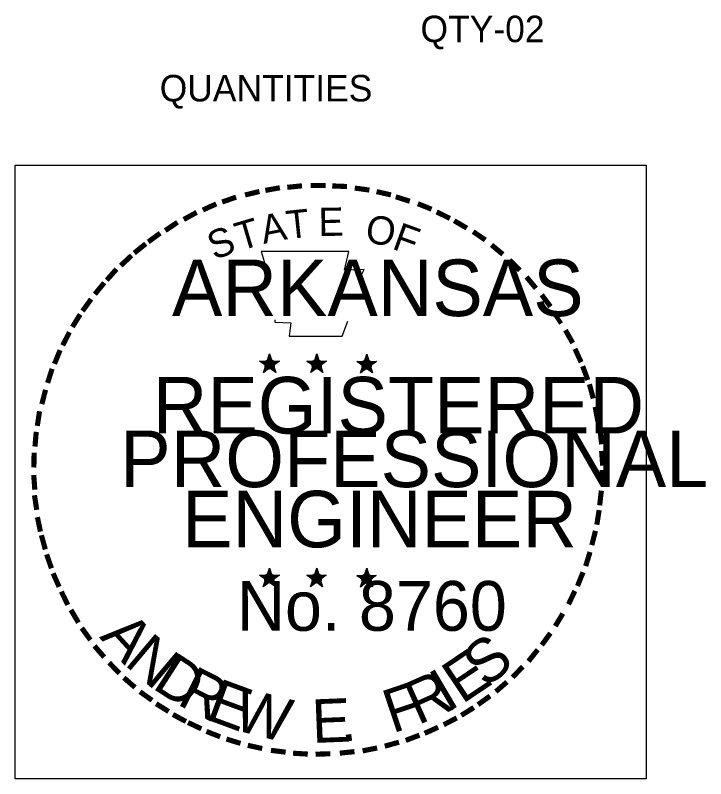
# Model space of a CAD drawing. Extents: x 1226657 to 1228145, y 151309 to 152305.
# Drawn here: x 1227992.6 to 1228145.3, y 152136.7 to 152305.5 of the extents above; entities that cross this region are included whole.
import ezdxf

# ---------------------------------------------------------------- set-up
doc = ezdxf.new("R2010")
doc.units = 0
for name, color, linetype in [('R_Border', 7, 'Continuous'), ('R_Border PE', 7, 'Continuous'), ('R_Border Prem', 7, 'Continuous')]:
    doc.layers.add(name, color=color, linetype=linetype)

msp = doc.modelspace()

# ---------------------------------------------------------------- linework, layer by layer
at = {"layer": 'R_Border PE'}
for p, q in [((1228048.84, 152230.69), (1228048.53, 152229.13)), ((1228048.84, 152230.69), (1228048.59, 152229.06)), ((1228048.84, 152230.69), (1228048.78, 152229.13)), ((1228048.84, 152228.38), (1228048.84, 152230.69)), ((1228048.84, 152230.69), (1228049.28, 152229.06)), ((1228048.84, 152230.69), (1228049.15, 152229.13)), ((1228048.84, 152230.69), (1228049.03, 152229.13)), ((1228059.28, 152230.69), (1228058.97, 152229.13)), ((1228059.28, 152230.69), (1228059.03, 152229.06)), ((1228059.28, 152230.69), (1228059.15, 152229.13)), ((1228059.28, 152228.38), (1228059.28, 152230.69)), ((1228059.28, 152230.69), (1228059.72, 152229.06)), ((1228059.28, 152230.69), (1228059.59, 152229.13)), ((1228059.28, 152230.69), (1228059.4, 152229.13)), ((1228070.34, 152230.56), (1228069.97, 152229.06)), ((1228070.34, 152230.56), (1228070.09, 152229)), ((1228070.34, 152230.56), (1228070.22, 152229)), ((1228070.34, 152228.31), (1228070.34, 152230.56)), ((1228070.34, 152230.56), (1228070.78, 152229)), ((1228070.34, 152230.56), (1228070.65, 152229)), ((1228070.34, 152230.56), (1228070.47, 152229.06)), ((1228046.65, 152229.06), (1228048.84, 152228.38)), ((1228046.65, 152229.06), (1228048.28, 152228.94)), ((1228046.65, 152229.06), (1228048.28, 152228.81)), ((1228046.65, 152229.06), (1228048.22, 152228.69)), ((1228046.65, 152229.06), (1228048.22, 152228.44)), ((1228046.65, 152229.06), (1228048.15, 152228.31)), ((1228046.65, 152229.06), (1228048.15, 152228.19)), ((1228047.53, 152226.5), (1228048.84, 152228.38)), ((1228047.53, 152226.5), (1228048.22, 152228.25)), ((1228047.53, 152226.5), (1228048.28, 152228.06)), ((1228047.53, 152226.5), (1228048.4, 152228)), ((1228047.53, 152226.5), (1228048.84, 152227.88)), ((1228047.53, 152226.5), (1228048.59, 152227.81)), ((1228047.53, 152226.5), (1228048.9, 152227.69)), ((1228051.03, 152229.06), (1228048.84, 152228.38)), ((1228050.22, 152226.5), (1228048.84, 152228.38)), ((1228050.22, 152226.5), (1228048.84, 152227.88)), ((1228050.22, 152226.5), (1228048.84, 152227.69)), ((1228051.03, 152229.06), (1228049.09, 152228.94)), ((1228050.22, 152226.5), (1228049.09, 152227.81)), ((1228051.03, 152229.06), (1228049.22, 152228.75)), ((1228051.03, 152229.06), (1228049.22, 152228.63)), ((1228050.22, 152226.5), (1228049.28, 152228.06)), ((1228050.22, 152226.5), (1228049.34, 152228.31)), ((1228050.22, 152226.5), (1228049.47, 152228.38)), ((1228051.03, 152229.06), (1228049.65, 152228.5)), ((1228051.03, 152229.06), (1228049.78, 152228.44)), ((1228051.03, 152229.06), (1228049.84, 152228.38)), ((1228057.09, 152229.06), (1228059.28, 152228.38)), ((1228057.09, 152229.06), (1228058.72, 152228.94)), ((1228057.09, 152229.06), (1228058.72, 152228.81)), ((1228057.09, 152229.06), (1228058.65, 152228.69)), ((1228057.09, 152229.06), (1228058.59, 152228.44)), ((1228057.09, 152229.06), (1228058.59, 152228.31)), ((1228057.09, 152229.06), (1228058.59, 152228.19)), ((1228057.97, 152226.5), (1228059.28, 152228.38)), ((1228057.97, 152226.5), (1228058.65, 152228.25)), ((1228057.97, 152226.5), (1228058.72, 152228.06)), ((1228057.97, 152226.5), (1228058.84, 152228)), ((1228057.97, 152226.5), (1228059.28, 152227.88)), ((1228057.97, 152226.5), (1228059.03, 152227.81)), ((1228057.97, 152226.5), (1228059.34, 152227.69)), ((1228061.47, 152229.06), (1228059.28, 152228.38)), ((1228060.65, 152226.5), (1228059.28, 152228.38)), ((1228060.65, 152226.5), (1228059.28, 152227.88)), ((1228060.65, 152226.5), (1228059.28, 152227.69)), ((1228061.47, 152229.06), (1228059.53, 152228.94)), ((1228060.65, 152226.5), (1228059.53, 152227.81)), ((1228061.47, 152229.06), (1228059.65, 152228.75)), ((1228061.47, 152229.06), (1228059.65, 152228.63)), ((1228060.65, 152226.5), (1228059.72, 152228.06)), ((1228060.65, 152226.5), (1228059.78, 152228.31)), ((1228060.65, 152226.5), (1228059.9, 152228.38)), ((1228061.47, 152229.06), (1228060.09, 152228.5)), ((1228061.47, 152229.06), (1228060.22, 152228.44)), ((1228061.47, 152229.06), (1228060.28, 152228.38)), ((1228068.15, 152229), (1228070.34, 152228.31)), ((1228068.15, 152229), (1228069.78, 152228.81)), ((1228068.15, 152229), (1228069.72, 152228.69)), ((1228068.15, 152229), (1228069.72, 152228.63)), ((1228068.15, 152229), (1228069.65, 152228.38)), ((1228068.15, 152229), (1228069.65, 152228.25)), ((1228068.15, 152229), (1228069.65, 152228.13)), ((1228068.97, 152226.44), (1228070.34, 152228.31)), ((1228068.97, 152226.44), (1228069.72, 152228.19)), ((1228068.97, 152226.44), (1228069.78, 152228)), ((1228068.97, 152226.44), (1228069.9, 152227.94)), ((1228068.97, 152226.44), (1228070.34, 152227.81)), ((1228068.97, 152226.44), (1228070.09, 152227.75)), ((1228068.97, 152226.44), (1228070.4, 152227.63)), ((1228072.53, 152229), (1228070.34, 152228.31)), ((1228071.65, 152226.44), (1228070.34, 152228.31)), ((1228071.65, 152226.44), (1228070.34, 152227.81)), ((1228071.65, 152226.44), (1228070.34, 152227.63)), ((1228072.53, 152229), (1228070.59, 152228.88)), ((1228071.65, 152226.44), (1228070.59, 152227.75)), ((1228072.53, 152229), (1228070.72, 152228.69)), ((1228072.53, 152229), (1228070.72, 152228.56)), ((1228071.65, 152226.44), (1228070.78, 152228)), ((1228071.65, 152226.44), (1228070.84, 152228.25)), ((1228071.65, 152226.44), (1228070.97, 152228.25)), ((1228072.53, 152229), (1228071.15, 152228.44)), ((1228072.53, 152229), (1228071.22, 152228.38)), ((1228072.53, 152229), (1228071.34, 152228.31)), ((1228048.84, 152183.31), (1228048.47, 152181.81)), ((1228048.84, 152183.31), (1228048.59, 152181.75)), ((1228048.84, 152183.31), (1228048.72, 152181.75)), ((1228048.84, 152181.06), (1228048.84, 152183.31)), ((1228048.84, 152183.31), (1228049.28, 152181.75)), ((1228048.84, 152183.31), (1228049.15, 152181.75)), ((1228048.84, 152183.31), (1228048.97, 152181.75)), ((1228059.28, 152183.31), (1228058.9, 152181.81)), ((1228059.28, 152183.31), (1228059.03, 152181.75)), ((1228059.28, 152183.31), (1228059.15, 152181.75)), ((1228059.28, 152181.06), (1228059.28, 152183.31)), ((1228059.28, 152183.31), (1228059.65, 152181.75)), ((1228059.28, 152183.31), (1228059.59, 152181.75)), ((1228059.28, 152183.31), (1228059.4, 152181.75)), ((1228070.34, 152183.25), (1228069.97, 152181.69)), ((1228070.34, 152183.25), (1228070.09, 152181.69)), ((1228070.34, 152183.25), (1228070.22, 152181.69)), ((1228070.34, 152181), (1228070.34, 152183.25)), ((1228070.34, 152183.25), (1228070.72, 152181.69)), ((1228070.34, 152183.25), (1228070.65, 152181.69)), ((1228070.34, 152183.25), (1228070.47, 152181.69)), ((1228046.65, 152181.75), (1228048.84, 152181.06)), ((1228046.65, 152181.75), (1228048.28, 152181.56)), ((1228046.65, 152181.75), (1228048.22, 152181.44)), ((1228046.65, 152181.75), (1228048.22, 152181.38)), ((1228046.65, 152181.75), (1228048.15, 152181.13)), ((1228046.65, 152181.75), (1228048.15, 152181)), ((1228046.65, 152181.75), (1228048.15, 152180.88)), ((1228047.47, 152179.19), (1228048.84, 152181.06)), ((1228047.47, 152179.19), (1228048.22, 152180.94)), ((1228047.47, 152179.19), (1228048.28, 152180.69)), ((1228047.47, 152179.19), (1228048.4, 152180.63)), ((1228047.47, 152179.19), (1228048.84, 152180.56)), ((1228047.47, 152179.19), (1228048.59, 152180.5)), ((1228047.47, 152179.19), (1228048.84, 152180.38)), ((1228050.15, 152179.19), (1228048.78, 152180.38)), ((1228051.03, 152181.75), (1228048.84, 152181.06)), ((1228050.15, 152179.19), (1228048.84, 152181.06)), ((1228050.15, 152179.19), (1228048.84, 152180.5)), ((1228050.15, 152179.19), (1228049.03, 152180.5)), ((1228051.03, 152181.75), (1228049.09, 152181.63)), ((1228051.03, 152181.75), (1228049.22, 152181.44)), ((1228051.03, 152181.75), (1228049.22, 152181.31)), ((1228050.15, 152179.19), (1228049.28, 152181)), ((1228050.15, 152179.19), (1228049.28, 152180.75)), ((1228050.15, 152179.19), (1228049.47, 152181)), ((1228051.03, 152181.75), (1228049.59, 152181.19)), ((1228051.03, 152181.75), (1228049.72, 152181.13)), ((1228051.03, 152181.75), (1228049.84, 152181)), ((1228057.09, 152181.75), (1228059.28, 152181.06)), ((1228057.09, 152181.75), (1228058.65, 152181.56)), ((1228057.09, 152181.75), (1228058.65, 152181.44)), ((1228057.09, 152181.75), (1228058.65, 152181.38)), ((1228057.09, 152181.75), (1228058.59, 152181.13)), ((1228057.09, 152181.75), (1228058.59, 152181)), ((1228057.09, 152181.75), (1228058.59, 152180.88)), ((1228057.9, 152179.19), (1228059.28, 152181.06)), ((1228057.9, 152179.19), (1228058.65, 152180.94)), ((1228057.9, 152179.19), (1228058.72, 152180.69)), ((1228057.9, 152179.19), (1228058.84, 152180.63)), ((1228057.9, 152179.19), (1228059.28, 152180.56)), ((1228057.9, 152179.19), (1228059.03, 152180.5)), ((1228057.9, 152179.19), (1228059.28, 152180.38)), ((1228060.59, 152179.19), (1228059.22, 152180.38)), ((1228061.4, 152181.75), (1228059.28, 152181.06)), ((1228060.59, 152179.19), (1228059.28, 152181.06)), ((1228060.59, 152179.19), (1228059.28, 152180.5)), ((1228060.59, 152179.19), (1228059.47, 152180.5)), ((1228061.4, 152181.75), (1228059.53, 152181.63)), ((1228061.4, 152181.75), (1228059.65, 152181.44)), ((1228061.4, 152181.75), (1228059.65, 152181.31)), ((1228060.59, 152179.19), (1228059.72, 152181)), ((1228060.59, 152179.19), (1228059.72, 152180.75)), ((1228060.59, 152179.19), (1228059.9, 152181)), ((1228061.4, 152181.75), (1228060.03, 152181.19)), ((1228061.4, 152181.75), (1228060.15, 152181.13)), ((1228061.4, 152181.75), (1228060.28, 152181)), ((1228068.15, 152181.69), (1228070.34, 152181)), ((1228068.15, 152181.69), (1228069.72, 152181.5)), ((1228068.15, 152181.69), (1228069.72, 152181.38)), ((1228068.15, 152181.69), (1228069.65, 152181.25)), ((1228068.15, 152181.69), (1228069.65, 152181.06)), ((1228068.15, 152181.69), (1228069.59, 152180.88)), ((1228068.15, 152181.69), (1228069.59, 152180.75)), ((1228068.97, 152179.13), (1228070.34, 152181)), ((1228068.97, 152179.13), (1228069.65, 152180.88)), ((1228068.97, 152179.13), (1228069.72, 152180.63)), ((1228068.97, 152179.13), (1228069.9, 152180.56)), ((1228068.97, 152179.13), (1228070.09, 152180.44)), ((1228068.97, 152179.13), (1228070.28, 152180.44)), ((1228071.65, 152179.13), (1228070.28, 152180.44)), ((1228072.47, 152181.69), (1228070.34, 152181)), ((1228071.65, 152179.13), (1228070.34, 152181)), ((1228071.65, 152179.13), (1228070.53, 152180.44)), ((1228072.47, 152181.69), (1228070.59, 152181.56)), ((1228072.47, 152181.69), (1228070.72, 152181.38)), ((1228072.47, 152181.69), (1228070.72, 152181.25)), ((1228071.65, 152179.13), (1228070.72, 152180.63)), ((1228071.65, 152179.13), (1228070.78, 152180.94)), ((1228071.65, 152179.13), (1228070.9, 152180.94)), ((1228072.47, 152181.69), (1228071.09, 152181.13)), ((1228072.47, 152181.69), (1228071.22, 152181)), ((1228072.47, 152181.69), (1228071.28, 152180.94)), ((1228068.97, 152179.13), (1228070.34, 152180.31)), ((1228071.65, 152179.13), (1228070.28, 152180.25))]:
    msp.add_line(p, q, dxfattribs=at)
for points in [[(1228046.97, 152253.31), (1228048.59, 152248.13)], [(1228068.9, 152247.56), (1228069.78, 152249.31), (1228065.47, 152249.19), (1228066.4, 152253.31), (1228046.97, 152253.31)], [(1228050.03, 152238.19), (1228050.03, 152237.63), (1228053.53, 152237.5), (1228053.22, 152234.56), (1228064.9, 152234.56), (1228066.15, 152237.88)], [(1228048.84, 152230.69), (1228050.22, 152226.5), (1228046.65, 152229.06), (1228051.03, 152229.06), (1228047.53, 152226.5), (1228048.84, 152230.69)], [(1228059.28, 152230.69), (1228060.65, 152226.5), (1228057.09, 152229.06), (1228061.47, 152229.06), (1228057.97, 152226.5), (1228059.28, 152230.69)], [(1228070.34, 152230.56), (1228071.65, 152226.44), (1228068.15, 152229), (1228072.53, 152229), (1228068.97, 152226.44), (1228070.34, 152230.56)], [(1228048.84, 152183.31), (1228050.15, 152179.19), (1228046.65, 152181.75), (1228051.03, 152181.75), (1228047.47, 152179.19), (1228048.84, 152183.31)], [(1228059.28, 152183.31), (1228060.59, 152179.19), (1228057.09, 152181.75), (1228061.4, 152181.75), (1228057.9, 152179.19), (1228059.28, 152183.31)], [(1228070.34, 152183.25), (1228071.65, 152179.13), (1228068.15, 152181.69), (1228072.47, 152181.69), (1228068.97, 152179.13), (1228070.34, 152183.25)]]:
    msp.add_lwpolyline(points, dxfattribs=at)
for centre, radius in [((1228048.86, 152228.37), 1.08), ((1228048.86, 152228.37), 0.975), ((1228048.86, 152228.37), 0.904), ((1228059.29, 152228.37), 1.08), ((1228059.29, 152228.37), 0.975), ((1228059.29, 152228.37), 0.904), ((1228070.34, 152228.3), 1.08), ((1228070.34, 152228.3), 0.975), ((1228048.86, 152228.37), 0.83), ((1228048.86, 152228.37), 0.723), ((1228048.86, 152228.37), 0.672), ((1228048.86, 152228.37), 0.619), ((1228048.86, 152228.37), 0.533), ((1228048.86, 152228.37), 0.467), ((1228048.86, 152228.37), 0.388), ((1228048.86, 152228.37), 0.31), ((1228048.86, 152228.37), 0.231), ((1228048.86, 152228.37), 0.185), ((1228048.86, 152228.37), 0.0901), ((1228059.29, 152228.37), 0.83), ((1228059.29, 152228.37), 0.723), ((1228059.29, 152228.37), 0.672), ((1228059.29, 152228.37), 0.619), ((1228059.29, 152228.37), 0.533), ((1228059.29, 152228.37), 0.467), ((1228059.29, 152228.37), 0.388), ((1228059.29, 152228.37), 0.31), ((1228059.29, 152228.37), 0.231), ((1228059.29, 152228.37), 0.185), ((1228059.29, 152228.37), 0.0901), ((1228070.34, 152228.3), 0.904), ((1228070.34, 152228.3), 0.83), ((1228070.34, 152228.3), 0.723), ((1228070.34, 152228.3), 0.672), ((1228070.34, 152228.3), 0.619), ((1228070.34, 152228.3), 0.533), ((1228070.34, 152228.3), 0.467), ((1228070.34, 152228.3), 0.388), ((1228070.34, 152228.3), 0.31), ((1228070.34, 152228.3), 0.231), ((1228070.34, 152228.3), 0.185), ((1228070.34, 152228.3), 0.0901), ((1228048.83, 152181.04), 1.08), ((1228048.83, 152181.04), 0.975), ((1228059.27, 152181.04), 1.08), ((1228059.27, 152181.04), 0.975), ((1228070.31, 152180.97), 1.08), ((1228048.83, 152181.04), 0.904), ((1228048.83, 152181.04), 0.83), ((1228048.83, 152181.04), 0.723), ((1228048.83, 152181.04), 0.672), ((1228048.83, 152181.04), 0.619), ((1228048.83, 152181.04), 0.533), ((1228048.83, 152181.04), 0.467), ((1228048.83, 152181.04), 0.388), ((1228048.83, 152181.04), 0.31), ((1228048.83, 152181.04), 0.231), ((1228048.83, 152181.04), 0.185), ((1228048.83, 152181.04), 0.0901), ((1228059.27, 152181.04), 0.904), ((1228059.27, 152181.04), 0.83), ((1228059.27, 152181.04), 0.723), ((1228059.27, 152181.04), 0.672), ((1228059.27, 152181.04), 0.619), ((1228059.27, 152181.04), 0.533), ((1228059.27, 152181.04), 0.467), ((1228059.27, 152181.04), 0.388), ((1228059.27, 152181.04), 0.31), ((1228059.27, 152181.04), 0.231), ((1228059.27, 152181.04), 0.185), ((1228059.27, 152181.04), 0.0901), ((1228070.31, 152180.97), 0.975), ((1228070.31, 152180.97), 0.904), ((1228070.31, 152180.97), 0.83), ((1228070.31, 152180.97), 0.723), ((1228070.31, 152180.97), 0.672), ((1228070.31, 152180.97), 0.619), ((1228070.31, 152180.97), 0.533), ((1228070.31, 152180.97), 0.467), ((1228070.31, 152180.97), 0.388), ((1228070.31, 152180.97), 0.31), ((1228070.31, 152180.97), 0.231), ((1228070.31, 152180.97), 0.185), ((1228070.31, 152180.97), 0.0901)]:
    msp.add_circle(centre, radius, dxfattribs=at)
at = {"layer": 'R_Border Prem'}
msp.add_lwpolyline([(1227992.62, 152272.36), (1228132.12, 152272.36), (1228132.12, 152136.74), (1227992.62, 152136.74)], close=True, dxfattribs=at)

# ---------------------------------------------------------------- texts
at = {"layer": 'R_Border'}
for s, height, p in [('QTY-02', 5.861, (1228082.24, 152299.55)), ('QUANTITIES', 5.862, (1228024.56, 152286.45))]:
    msp.add_text(s, height=height, dxfattribs=at).set_placement(p)
at = {"layer": 'R_Border PE'}
for s, height, rotation, p in [('-', 10, 5.8968, (1228052.59, 152263.56)), ('-', 10, 0.1862, (1228057.4, 152264)), ('-', 10, 357.743, (1228061.97, 152263.94)), ('-', 10, 13.6302, (1228043.78, 152261.88)), ('-', 10, 10.2193, (1228048.03, 152262.88)), ('-', 10, 352.1617, (1228066.59, 152263.56)), ('-', 10, 347.2049, (1228071.09, 152262.88)), ('-', 10, 19.1761, (1228039.09, 152260.38)), ('-', 10, 342.3362, (1228075.03, 152261.88)), ('-', 10, 24.3072, (1228035.15, 152258.69)), ('-', 10, 337.8551, (1228079.65, 152260.5)), ('-', 10, 28.7918, (1228031.22, 152256.69)), ('A', 6.25, 11.2132, (1228047.53, 152254.94)), ('T', 6.25, 6.0228, (1228052.84, 152256)), ('E', 6.25, 0.8323, (1228059.72, 152256.69)), ('-', 10, 334.1211, (1228083.59, 152258.81)), ('-', 10, 34.0636, (1228027.47, 152254.38)), ('T', 6.25, 16.4036, (1228042.34, 152253.38)), ('O', 6.25, 350.4515, (1228069.78, 152255.38)), ('-', 10, 329.6409, (1228087.22, 152257.06)), ('S', 6.25, 21.594, (1228036.65, 152251.31)), ('F', 6.25, 340.0707, (1228075.72, 152253.94)), ('-', 10, 325.8627, (1228091.22, 152254.81)), ('-', 10, 36.2317, (1228023.84, 152251.94)), ('-', 10, 38.9507, (1228020.9, 152249.56)), ('-', 10, 320.5297, (1228095.03, 152252.13)), ('-', 10, 42.9622, (1228018.15, 152246.94)), ('-', 10, 315.5786, (1228098.78, 152249.06)), ('-', 10, 48.423, (1228015.34, 152243.94)), ('-', 10, 309.8797, (1228102.34, 152245.63)), ('-', 10, 50.6142, (1228012.84, 152240.94)), ('-', 10, 54.2325, (1228010.28, 152237.38)), ('-', 10, 306.6522, (1228105.59, 152241.88)), ('-', 10, 58.0706, (1228008.22, 152234.06)), ('-', 8.75, 303.6753, (1228108.65, 152238.31)), ('-', 10, 299.6684, (1228110.65, 152234.5)), ('-', 10, 62.8713, (1228006.28, 152230.25)), ('-', 10, 67.7743, (1228004.65, 152226.44)), ('-', 10, 294.6628, (1228112.65, 152230.69)), ('-', 10, 290.5728, (1228114.28, 152227.13)), ('-', 10, 72.3945, (1228003.28, 152222.5)), ('-', 10, 75.461, (1228002.09, 152218)), ('-', 10, 285.1233, (1228115.72, 152223.5)), ('-', 10, 81.2013, (1228001.22, 152213.56)), ('-', 10, 280.5493, (1228116.97, 152218.81)), ('-', 10, 85.1863, (1228000.78, 152209.25)), ('-', 10, 276.5962, (1228118.03, 152214.06)), ('-', 10, 274.3301, (1228118.4, 152209.5)), ('-', 10, 89.0622, (1228000.59, 152204.88)), ('-', 10, 269.9407, (1228118.59, 152205.56)), ('-', 10, 94.1959, (1228000.84, 152200.31)), ('-', 10, 98.9479, (1228001.28, 152196.19)), ('-', 10, 263.5172, (1228118.47, 152201.44)), ('-', 10, 260.9953, (1228118.03, 152197.31)), ('-', 10, 101.7149, (1228002.09, 152191.56)), ('-', 10, 105.4578, (1228003.15, 152187.88)), ('-', 10, 255.7626, (1228117.34, 152193.06)), ('-', 10, 109.0874, (1228004.47, 152183.94)), ('-', 10, 252.8681, (1228116.22, 152188.56)), ('-', 10, 114.0643, (1228006.09, 152180.19)), ('-', 10, 247.8887, (1228114.84, 152184.38)), ('-', 10, 115.7289, (1228007.97, 152176.31)), ('-', 10, 244.6197, (1228113.15, 152180.44)), ('-', 10, 120.4471, (1228010.22, 152172.69)), ('-', 10, 239.0712, (1228110.72, 152175.75)), ('-', 10, 125.8934, (1228012.72, 152169.19)), ('A', 9.62, 312.4727, (1228011.09, 152168)), ('N', 9.62, 319.8362, (1228016.52, 152162.06)), ('-', 10, 233.8452, (1228108.22, 152171.69)), ('S', 9.62, 39.723, (1228096.76, 152156.6)), ('-', 10, 130.7181, (1228015.59, 152165.69)), ('E', 9.62, 33.8878, (1228091.42, 152153.11)), ('-', 10, 231.2538, (1228105.53, 152168.13)), ('D', 9.62, 327.1996, (1228022.67, 152156.88)), ('-', 10, 134.2238, (1228018.84, 152162.31)), ('-', 10, 225.7653, (1228102.53, 152164.63)), ('R', 9.62, 333.1738, (1228028.11, 152153.28)), ('I', 9.62, 30.5534, (1228088.22, 152151.37)), ('-', 10, 138.9338, (1228022.09, 152159.44)), ('E', 9.62, 339.7037, (1228034.46, 152150.01)), ('R', 9.62, 24.0235, (1228081.68, 152148.52)), ('-', 10, 221.0851, (1228099.28, 152161.44)), ('W', 9.62, 345.5389, (1228040.41, 152147.72)), ('F', 9.62, 18.6051, (1228076.04, 152146.72)), ('-', 10, 144.6463, (1228025.59, 152156.88)), ('-', 10, 215.7363, (1228095.84, 152158.5)), ('-', 10, 148.0898, (1228029.09, 152154.56)), ('E', 9.62, 2.2804, (1228058.38, 152144.63)), ('-', 10, 212.2491, (1228092.47, 152156.06)), ('-', 10, 151.5704, (1228032.72, 152152.5)), ('-', 10, 207.3568, (1228089.03, 152153.88)), ('-', 10, 154.6002, (1228035.97, 152151)), ('-', 10, 204.2516, (1228085.09, 152151.88)), ('-', 10, 158.5612, (1228039.9, 152149.38)), ('.', 9.62, 8.1156, (1228064.75, 152144.8)), ('-', 10, 200.7184, (1228081.22, 152150.19)), ('-', 10, 162.7983, (1228044.15, 152148.06)), ('-', 10, 195.4743, (1228077.03, 152148.69)), ('-', 10, 167.5555, (1228048.65, 152147.06)), ('-', 10, 173.1155, (1228053.47, 152146.38)), ('-', 10, 185.8167, (1228067.84, 152146.63)), ('-', 10, 191.2858, (1228072.47, 152147.44)), ('-', 10, 176.5183, (1228058.15, 152146)), ('-', 10, 181.5918, (1228062.78, 152146.13))]:
    msp.add_text(s, height=height, rotation=rotation, dxfattribs=at).set_placement(p)
for s, height, p in [('ARKANSAS', 12.5, (1228027.28, 152239)), ('REGISTERED', 12.5, (1228023.03, 152213.06)), ('PROFESSIONAL', 12.4999, (1228015.84, 152201.19)), ('ENGINEER', 12.5, (1228029.53, 152187.88)), ('No. 8760', 11, (1228041.64, 152169.44))]:
    msp.add_text(s, height=height, dxfattribs=at).set_placement(p)

doc.saveas('drawing.dxf')
